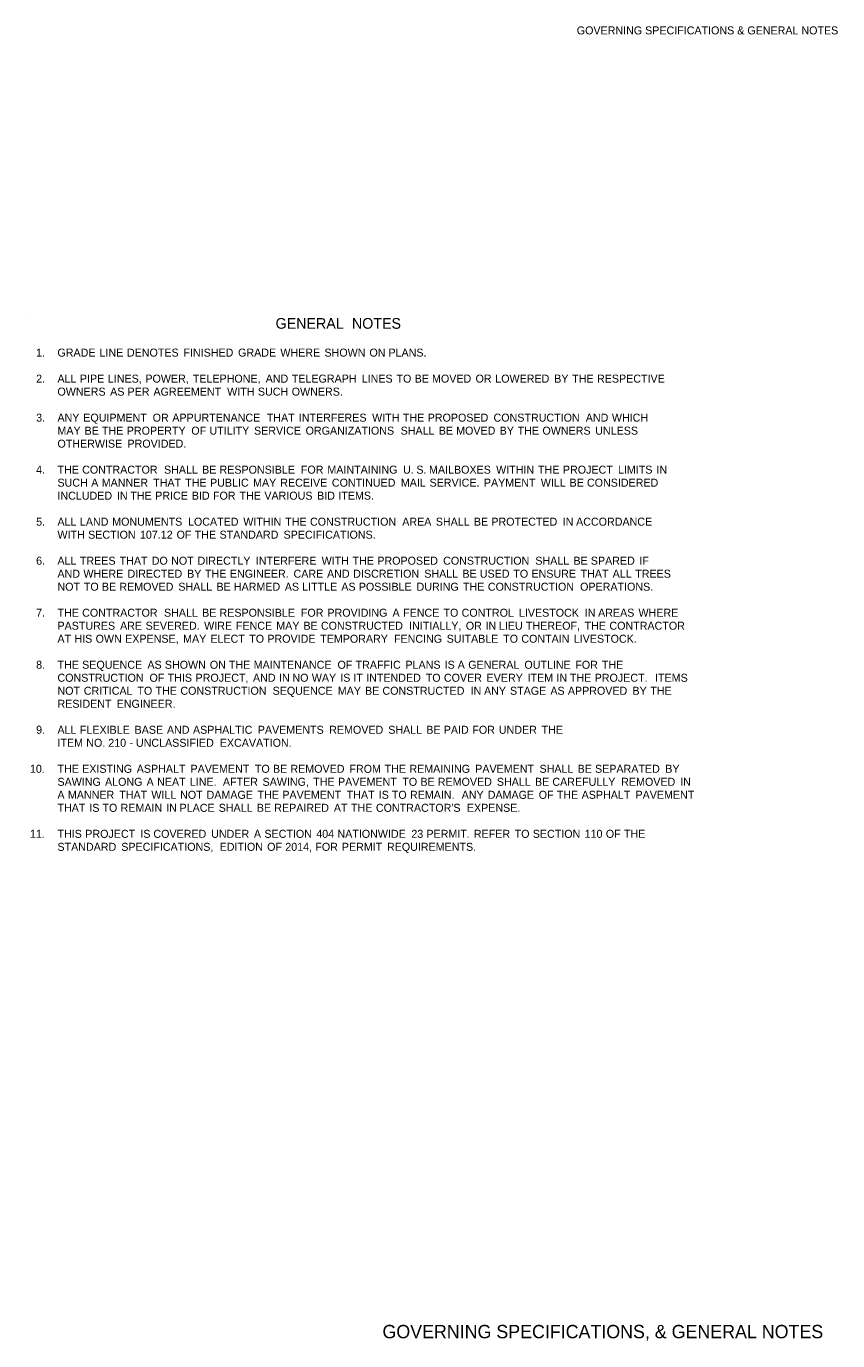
# Model space of a CAD drawing. Extents: x -1397 to 1646, y -1034 to 1018.
import ezdxf

# ---------------------------------------------------------------- set-up
doc = ezdxf.new("R2010")
doc.units = 0
for name, color, linetype in [('Default', 7, 'Continuous'), ('R_Border', 7, 'Continuous'), ('R_Border Prem', 7, 'Continuous')]:
    doc.layers.add(name, color=color, linetype=linetype)

msp = doc.modelspace()

# ---------------------------------------------------------------- linework, layer by layer
at = {"layer": 'Default'}
msp.add_line((428.1, 504), (428.1, 504), dxfattribs=at)

# ---------------------------------------------------------------- texts
for s, height, p in [('GENERAL', 16, (802.2, 482.8)), (' NOTES', 16, (910.8, 482.8)), ('1.', 12, (442.9, 441)), ('GRADE', 12, (474.9, 441)), (' LINE', 12, (533.6, 441)), (' DENOTES', 12, (574.7, 441)), (' FINISHED', 12, (659.5, 441)), (' GRADE', 12, (741.5, 441)), (' WHERE', 12, (804.9, 441)), (' SHOWN', 12, (871.1, 441)), (' ON', 12, (938.6, 441)), (' PLANS.', 12, (967.1, 441)), ('2.', 12, (442.9, 402)), ('ALL', 12, (474.9, 402)), (' PIPE', 12, (504.1, 402)), (' LINES,', 12, (546.1, 402)), (' POWER,', 12, (602.4, 402)), (' TELEPHONE,', 12, (673.5, 402)), (' AND', 12, (782.9, 402)), (' TELEGRAPH', 12, (822.1, 402)), (' LINES', 12, (927, 402)), (' TO', 12, (979.2, 402)), (' BE', 12, (1006.4, 402)), (' MOVED', 12, (1032.5, 402)), (' OR', 12, (1097.8, 402)), (' LOWERED', 12, (1127.4, 402)), (' BY', 12, (1215.9, 402)), (' THE', 12, (1242.8, 402)), (' RESPECTIVE', 12, (1280.1, 402)), ('OWNERS', 12, (474.9, 382.5)), (' AS', 12, (549.5, 382.5)), (' PER', 12, (575.6, 382.5)), (' AGREEMENT', 12, (614.5, 382.5)), (' WITH', 12, (725.1, 382.5)), (' SUCH', 12, (771.2, 382.5)), (' OWNERS.', 12, (822, 382.5)), ('3.', 12, (442.9, 343.5)), ('ANY', 12, (474.9, 343.5)), (' EQUIPMENT', 12, (509.2, 343.5)), (' OR', 12, (613.3, 343.5)), (' APPURTENANCE', 12, (642.8, 343.5)), (' THAT', 12, (784.5, 343.5)), (' INTERFERES', 12, (832.6, 343.5)), (' WITH', 12, (942.6, 343.5)), (' THE', 12, (988.7, 343.5)), (' PROPOSED', 12, (1026, 343.5)), (' CONSTRUCTION', 12, (1124.8, 343.5)), (' AND', 12, (1263.2, 343.5)), (' WHICH', 12, (1302.4, 343.5)), ('MAY', 12, (474.9, 324)), (' BE', 12, (511.1, 324)), (' THE', 12, (537.2, 324)), (' PROPERTY', 12, (574.5, 324)), (' OF', 12, (671.3, 324)), (' UTILITY', 12, (698.5, 324)), (' SERVICE', 12, (765.4, 324)), (' ORGANIZATIONS', 12, (842.8, 324)), (' SHALL', 12, (985.4, 324)), (' BE', 12, (1042.6, 324)), (' MOVED', 12, (1068.7, 324)), (' BY', 12, (1134, 324)), (' THE', 12, (1160.9, 324)), (' OWNERS', 12, (1198.2, 324)), (' UNLESS', 12, (1277.4, 324)), ('OTHERWISE', 12, (474.9, 304.5)), (' PROVIDED.', 12, (575.5, 304.5)), ('4.', 12, (442.9, 265.5)), ('THE', 12, (474.9, 265.5)), (' CONTRACTOR', 12, (507.5, 265.5)), (' SHALL', 12, (630.3, 265.5)), (' BE', 12, (687.5, 265.5)), (' RESPONSIBLE', 12, (713.6, 265.5)), (' FOR', 12, (835.7, 265.5)), (' MAINTAINING', 12, (875.5, 265.5)), (' U.', 12, (989, 265.5)), (' S.', 12, (1009, 265.5)), (' MAILBOXES', 12, (1028, 265.5)), (' WITHIN', 12, (1128.7, 265.5)), (' THE', 12, (1191.6, 265.5)), (' PROJECT', 12, (1228.9, 265.5)), (' LIMITS', 12, (1311.5, 265.5)), (' IN', 12, (1369.3, 265.5)), ('SUCH', 12, (474.9, 246)), (' A', 12, (521.1, 246)), (' MANNER', 12, (536.9, 246)), (' THAT', 12, (614, 246)), (' THE', 12, (662.1, 246)), (' PUBLIC', 12, (699.4, 246)), (' MAY', 12, (764, 246)), (' RECEIVE', 12, (804.8, 246)), (' CONTINUED', 12, (882.2, 246)), (' MAIL', 12, (985.7, 246)), (' SERVICE.', 12, (1028.8, 246)), (' PAYMENT', 12, (1110.3, 246)), (' WILL', 12, (1195.7, 246)), (' BE', 12, (1238.9, 246)), (' CONSIDERED', 12, (1265, 246)), ('INCLUDED', 12, (474.9, 226.5)), (' IN', 12, (559.7, 226.5)), (' THE', 12, (579.8, 226.5)), (' PRICE', 12, (617.1, 226.5)), (' BID', 12, (672.1, 226.5)), (' FOR', 12, (703.8, 226.5)), (' THE', 12, (743.6, 226.5)), (' VARIOUS', 12, (780.9, 226.5)), (' BID', 12, (860.1, 226.5)), (' ITEMS.', 12, (891.9, 226.5)), ('5.', 12, (442.9, 187.5)), ('ALL', 12, (474.9, 187.5)), (' LAND', 12, (504.1, 187.5)), (' MONUMENTS', 12, (552.6, 187.5)), (' LOCATED', 12, (666.3, 187.5)), (' WITHIN', 12, (749.3, 187.5)), (' THE', 12, (812.1, 187.5)), (' CONSTRUCTION', 12, (849.4, 187.5)), (' AREA', 12, (987.8, 187.5)), (' SHALL', 12, (1038.2, 187.5)), (' BE', 12, (1095.3, 187.5)), (' PROTECTED', 12, (1121.5, 187.5)), (' IN', 12, (1228.6, 187.5)), (' ACCORDANCE', 12, (1248.7, 187.5)), ('WITH', 12, (474.9, 168)), (' SECTION', 12, (516.4, 168)), (' 107.12', 12, (594.2, 168)), (' OF', 12, (649.2, 168)), (' THE', 12, (676.4, 168)), (' STANDARD', 12, (713.7, 168)), (' SPECIFICATIONS.', 12, (809.7, 168)), ('6.', 12, (442.9, 129)), ('ALL', 12, (474.9, 129)), (' TREES', 12, (504.1, 129)), (' THAT', 12, (563.8, 129)), (' DO', 12, (611.9, 129)), (' NOT', 12, (641, 129)), (' DIRECTLY', 12, (680.7, 129)), (' INTERFERE', 12, (768.1, 129)), (' WITH', 12, (866.9, 129)), (' THE', 12, (913.1, 129)), (' PROPOSED', 12, (950.4, 129)), (' CONSTRUCTION', 12, (1049.2, 129)), (' SHALL', 12, (1187.5, 129)), (' BE', 12, (1244.7, 129)), (' SPARED', 12, (1270.8, 129)), (' IF', 12, (1343.6, 129)), ('AND', 12, (474.9, 109.5)), (' WHERE', 12, (509.4, 109.5)), (' DIRECTED', 12, (575.6, 109.5)), (' BY', 12, (665, 109.5)), (' THE', 12, (691.9, 109.5)), (' ENGINEER.', 12, (729.2, 109.5)), (' CARE', 12, (824.7, 109.5)), (' AND', 12, (875, 109.5)), (' DISCRETION', 12, (914.2, 109.5)), (' SHALL', 12, (1020.9, 109.5)), (' BE', 12, (1078.1, 109.5)), (' USED', 12, (1104.2, 109.5)), (' TO', 12, (1154.5, 109.5)), (' ENSURE', 12, (1181.7, 109.5)), (' THAT', 12, (1255.4, 109.5)), (' ALL', 12, (1303.5, 109.5)), (' TREES', 12, (1337.4, 109.5)), ('NOT', 12, (474.9, 90)), (' TO', 12, (510, 90)), (' BE', 12, (537.1, 90)), (' REMOVED', 12, (563.3, 90)), (' SHALL', 12, (651.8, 90)), (' BE', 12, (709, 90)), (' HARMED', 12, (735.1, 90)), (' AS', 12, (811.6, 90)), (' LITTLE', 12, (837.7, 90)), (' AS', 12, (896.4, 90)), (' POSSIBLE', 12, (922.6, 90)), (' DURING', 12, (1009.3, 90)), (' THE', 12, (1079, 90)), (' CONSTRUCTION', 12, (1116.3, 90)), (' OPERATIONS.', 12, (1254.7, 90)), ('7.', 12, (442.9, 51)), ('THE', 12, (474.9, 51)), (' CONTRACTOR', 12, (507.5, 51)), (' SHALL', 12, (630.3, 51)), (' BE', 12, (687.5, 51)), (' RESPONSIBLE', 12, (713.6, 51)), (' FOR', 12, (835.7, 51)), (' PROVIDING', 12, (875.5, 51)), (' A', 12, (973.2, 51)), (' FENCE', 12, (989.1, 51)), (' TO', 12, (1049.7, 51)), (' CONTROL', 12, (1076.9, 51)), (' LIVESTOCK', 12, (1162.9, 51)), (' IN', 12, (1261.7, 51)), (' AREAS', 12, (1281.7, 51)), (' WHERE', 12, (1342.3, 51)), ('PASTURES', 12, (474.9, 31.5)), (' ARE', 12, (564.4, 31.5)), (' SEVERED.', 12, (602.7, 31.5)), (' WIRE', 12, (690.6, 31.5)), (' FENCE', 12, (738.2, 31.5)), (' MAY', 12, (798.8, 31.5)), (' BE', 12, (839.6, 31.5)), (' CONSTRUCTED', 12, (865.8, 31.5)), (' INITIALLY,', 12, (998.1, 31.5)), (' OR', 12, (1083.2, 31.5)), (' IN', 12, (1112.8, 31.5)), (' LIEU', 12, (1132.9, 31.5)), (' THEREOF,', 12, (1173.4, 31.5)), (' THE', 12, (1261.4, 31.5)), (' CONTRACTOR', 12, (1298.7, 31.5)), ('AT', 12, (474.9, 12)), (' HIS', 12, (496, 12)), (' OWN', 12, (527.7, 12)), (' EXPENSE,', 12, (572, 12)), (' MAY', 12, (659, 12)), (' ELECT', 12, (699.9, 12)), (' TO', 12, (758.2, 12)), (' PROVIDE', 12, (785.4, 12)), (' TEMPORARY', 12, (864.7, 12)), (' FENCING', 12, (975.4, 12)), (' SUITABLE', 12, (1054.5, 12)), (' TO', 12, (1139.3, 12)), (' CONTAIN', 12, (1166.5, 12)), (' LIVESTOCK.', 12, (1245.2, 12)), ('8.', 12, (442.9, -27)), ('THE', 12, (474.9, -27)), (' SEQUENCE', 12, (507.5, -27)), (' AS', 12, (605.4, -27)), (' SHOWN', 12, (631.6, -27)), (' ON', 12, (699.1, -27)), (' THE', 12, (727.6, -27)), (' MAINTENANCE', 12, (764.9, -27)), (' OF', 12, (890.7, -27)), (' TRAFFIC', 12, (917.8, -27)), (' PLANS', 12, (992.6, -27)), (' IS', 12, (1051.4, -27)), (' A', 12, (1071, -27)), (' GENERAL', 12, (1086.9, -27)), (' OUTLINE', 12, (1171.1, -27)), (' FOR', 12, (1247.5, -27)), (' THE', 12, (1287.3, -27)), ('CONSTRUCTION', 12, (474.9, -46.5)), (' OF', 12, (608.6, -46.5)), (' THIS', 12, (635.8, -46.5)), (' PROJECT,', 12, (677.7, -46.5)), (' AND', 12, (763.8, -46.5)), (' IN', 12, (803, -46.5)), (' NO', 12, (823, -46.5)), (' WAY', 12, (852.1, -46.5)), (' IS', 12, (894.8, -46.5)), (' IT', 12, (914.4, -46.5)), (' INTENDED', 12, (933.7, -46.5)), (' TO', 12, (1023.1, -46.5)), (' COVER', 12, (1050.3, -46.5)), (' EVERY', 12, (1114.4, -46.5)), (' ITEM', 12, (1175.8, -46.5)), (' IN', 12, (1219.2, -46.5)), (' THE', 12, (1239.3, -46.5)), (' PROJECT.', 12, (1276.6, -46.5)), ('  ITEMS', 12, (1362.7, -46.5)), ('NOT', 12, (474.9, -66)), (' CRITICAL', 12, (510, -66)), (' TO', 12, (590.4, -66)), (' THE', 12, (617.6, -66)), (' CONSTRUCTION', 12, (654.9, -66)), (' SEQUENCE', 12, (793.3, -66)), (' MAY', 12, (891.1, -66)), (' BE', 12, (932, -66)), (' CONSTRUCTED', 12, (958.1, -66)), (' IN', 12, (1090.4, -66)), (' ANY', 12, (1110.5, -66)), (' STAGE', 12, (1149.5, -66)), (' AS', 12, (1210.1, -66)), (' APPROVED', 12, (1236.3, -66)), (' BY', 12, (1333.2, -66)), (' THE', 12, (1360.1, -66)), ('RESIDENT', 12, (474.9, -85.5)), (' ENGINEER.', 12, (559.3, -85.5)), ('9.', 12, (442.9, -124.5)), ('ALL', 12, (474.9, -124.5)), (' FLEXIBLE', 12, (504.1, -124.5)), (' BASE', 12, (586.2, -124.5)), (' AND', 12, (634.7, -124.5)), (' ASPHALTIC', 12, (673.8, -124.5)), (' PAVEMENTS', 12, (771, -124.5)), (' REMOVED', 12, (878.2, -124.5)), (' SHALL', 12, (966.8, -124.5)), (' BE', 12, (1023.9, -124.5)), (' PAID', 12, (1050.1, -124.5)), (' FOR', 12, (1093, -124.5)), (' UNDER', 12, (1132.8, -124.5)), (' THE', 12, (1196.9, -124.5)), ('ITEM', 12, (474.9, -144)), (' NO.', 12, (513.7, -144)), (' 210', 12, (546.7, -144)), (' UNCLASSIFIED', 12, (588.2, -144)), (' EXCAVATION.', 12, (714, -144)), (' -', 12, (578.5, -144)), ('10.', 12, (433.6, -183)), ('THE', 12, (474.9, -183)), (' EXISTING', 12, (507.5, -183)), (' ASPHALT', 12, (589.4, -183)), (' PAVEMENT', 12, (670.1, -183)), (' TO', 12, (766.7, -183)), (' BE', 12, (793.9, -183)), (' REMOVED', 12, (820, -183)), (' FROM', 12, (908.6, -183)), (' THE', 12, (961.3, -183)), (' REMAINING', 12, (998.6, -183)), (' PAVEMENT', 12, (1097.3, -183)), (' SHALL', 12, (1193.8, -183)), (' BE', 12, (1251, -183)), (' SEPARATED', 12, (1277.1, -183)), (' BY', 12, (1382.5, -183)), ('SAWING', 12, (474.9, -202.5)), (' ALONG', 12, (541.8, -202.5)), (' A', 12, (604.2, -202.5)), (' NEAT', 12, (620, -202.5)), (' LINE.', 12, (669.1, -202.5)), ('  AFTER', 12, (714.2, -202.5)), (' SAWING,', 12, (778.2, -202.5)), (' THE', 12, (854.1, -202.5)), (' PAVEMENT', 12, (891.4, -202.5)), (' TO', 12, (987.9, -202.5)), (' BE', 12, (1015.1, -202.5)), (' REMOVED', 12, (1041.2, -202.5)), (' SHALL', 12, (1129.8, -202.5)), (' BE', 12, (1187, -202.5)), (' CAREFULLY', 12, (1213.1, -202.5)), (' REMOVED', 12, (1316.4, -202.5)), (' IN', 12, (1404.9, -202.5)), ('A', 12, (474.9, -222)), (' MANNER', 12, (486.1, -222)), (' THAT', 12, (563.2, -222)), (' WILL', 12, (611.3, -222)), (' NOT', 12, (654.5, -222)), (' DAMAGE', 12, (694.2, -222)), (' THE', 12, (770.6, -222)), (' PAVEMENT', 12, (807.9, -222)), (' THAT', 12, (904.5, -222)), (' IS', 12, (952.6, -222)), (' TO', 12, (972.2, -222)), (' REMAIN.', 12, (999.4, -222)), ('  ANY', 12, (1072.5, -222)), (' DAMAGE', 12, (1116.1, -222)), (' OF', 12, (1192.6, -222)), (' THE', 12, (1219.7, -222)), (' ASPHALT', 12, (1257, -222)), (' PAVEMENT', 12, (1337.8, -222)), ('THAT', 12, (474.9, -241.5)), (' IS', 12, (518.3, -241.5)), (' TO', 12, (538, -241.5)), (' REMAIN', 12, (565.2, -241.5)), (' IN', 12, (633.6, -241.5)), (' PLACE', 12, (653.7, -241.5)), (' SHALL', 12, (712.4, -241.5)), (' BE', 12, (769.6, -241.5)), (' REPAIRED', 12, (795.8, -241.5)), (' AT', 12, (885.2, -241.5)), (' THE', 12, (911, -241.5)), (" CONTRACTOR'S", 12, (948.3, -241.5)), (' EXPENSE.', 12, (1084.8, -241.5)), ('11.', 12, (433.6, -280.5)), ('THIS', 12, (474.9, -280.5)), (' PROJECT', 12, (512.2, -280.5)), (' IS', 12, (594.8, -280.5)), (' COVERED', 12, (614.4, -280.5)), (' UNDER', 12, (701.1, -280.5)), (' A', 12, (765.2, -280.5)), (' SECTION', 12, (781, -280.5)), (' 404', 12, (858.8, -280.5)), (' NATIONWIDE', 12, (890.6, -280.5)), (' 23', 12, (1001.5, -280.5)), (' PERMIT.', 12, (1024.1, -280.5)), (' REFER', 12, (1095.3, -280.5)), (' TO', 12, (1156.5, -280.5)), (' SECTION', 12, (1183.7, -280.5)), (' 110', 12, (1261.5, -280.5)), (' OF', 12, (1293.3, -280.5)), (' THE', 12, (1320.5, -280.5)), ('STANDARD', 12, (474.9, -300)), (' SPECIFICATIONS,', 12, (566.2, -300)), (' EDITION', 12, (713.8, -300)), (' OF', 12, (785.1, -300)), (' 2014,', 12, (812.3, -300)), (' FOR', 12, (857.4, -300)), (' PERMIT', 12, (897.2, -300)), (' REQUIREMENTS.', 12, (964.9, -300))]:
    msp.add_text(s, height=height, dxfattribs=at).set_placement(p)
at = {"layer": 'R_Border'}
msp.add_text('GOVERNING SPECIFICATIONS, & GENERAL NOTES', height=20, dxfattribs=at).set_placement((962.6, -1030.8))
at = {"layer": 'R_Border Prem'}
msp.add_text('GOVERNING SPECIFICATIONS & GENERAL NOTES', height=12, dxfattribs=at).set_placement((1254.2, 924.1))

doc.saveas('drawing.dxf')
